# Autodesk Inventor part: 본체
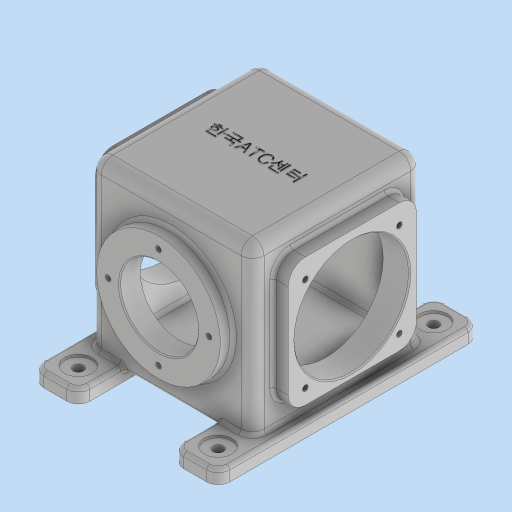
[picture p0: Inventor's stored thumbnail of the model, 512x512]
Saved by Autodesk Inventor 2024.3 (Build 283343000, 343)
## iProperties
Created: 2026-01
Part Number: 본체
Material: 일반
Document SubType Name: Modeling
Designer: PC2-02
Density: 1 g/cm^3
Appearance: 기본값
Author: PC2-02
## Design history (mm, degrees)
sketch "스케치1"
  geometry: L1 (-81, 114)-(81, 114); L2 (81, 114)-(81, -114); L3 (81, -114)-(-81, -114); L4 (-81, -114)-(-81, 114); 1 further point
  constraints: 8 end point, 2 parallel, 1 horizontal, 1 perpendicular
  dimensions: "d0" = 162 distance between parallel lines of L2 L4; "d1" = 81 distance from line of point (0, 0) L4; "d2" = 228 distance between parallel lines of L3 L1; "d3" = 114 distance from line of point (0, 0) L1
extrude "돌출1" new body sketch "스케치1" distance "d4" = 12; taper "d5" = 0 deg
sketch "스케치12"
  geometry: L1 (81, 114)-(-81, 114) reference; L2 (-81, -114)-(81, -114) reference; L3 (-41, 114)-(41, 114); L4 (41, 114)-(41, -114); L5 (41, -114)-(-41, -114); L6 (-41, -114)-(-41, 114); L7 (81, -114)-(81, 114) reference; L8 (-81, 114)-(-81, -114) reference; 3 further points
  constraints: 8 end point, 2 parallel, 2 point on line, 1 horizontal, 1 perpendicular
  dimensions: "d91" = 40 distance between parallel lines of L7 L4; "d92" = 40 distance between parallel lines of L8 L6
extrude "돌출7" cut sketch "스케치12" extent not by distance; stored distance "d93" = 0; taper "d94" = 0 deg
sketch "스케치2"
  geometry: L1 (71, 156)-(-71, 156); L2 (-71, 156)-(-71, 8); L3 (-71, 8)-(71, 8); L4 (71, 8)-(71, 156); L5 (81, 0)-(-81, 0) reference; 2 further points
  constraints: 8 end point, 2 parallel, 1 horizontal, 1 midpoint, 1 perpendicular
  dimensions: "d6" = 156 distance between parallel lines of L5 L1; "d7" = 142 distance between parallel lines of L2 L4; "d8" = 71 distance from line of point (0, 0) L4; "d90" = 8 distance between parallel lines of L5 L3
extrude "돌출2" join sketch "스케치2" stored distance "d9" = 148; taper "d10" = 0 deg
sketch "스케치3"
  geometry: L1 (-56, 140)-(56, 140); L2 (56, 140)-(56, 28); L3 (56, 28)-(-56, 28); L4 (-56, 28)-(-56, 140); L5 (-74, 156)-(-74, 12) reference; 2 further points
  constraints: 8 end point, 2 parallel, 1 horizontal, 1 midpoint, 1 perpendicular
  dimensions: "d11" = 112 distance between parallel lines of L2 L4; "d12" = 56 distance from line of point (0, 0) L4; "d13" = 112 distance between parallel lines of L3 L1; "d14" = 56 distance from line of point (-74, 84) L1
extrude "돌출3" join sketch "스케치3" stored distance "d15" = 168; taper "d16" = 0 deg
sketch "스케치4"
  geometry: L1 (-81, 0)-(81, 0) reference; C1 r 54 at (0, 82); 2 further points
  constraints: 1 centre point, 1 midpoint, 1 vertical alignment
  dimensions: "d17" = 108 diameter of C1; "d18" = 82 distance from line of L1 C1.centre
extrude "돌출4" join sketch "스케치4" distance "d19" = 11; taper "d20" = 0 deg
sketch "스케치6"
  geometry: L1 (-28, 56)-(-140, 56) reference; L2 (-140, 56)-(-140, -56) reference; L3 (0, -114)-(0, 114) reference; 2 further points
  dimensions: "d25" = 56 distance from line of L1 point (-82, 0); "d112" = 82 distance from line of L3 point (-82, 0)
hole "구멍1" sketch "스케치6" at (-82, 0) diameter "d27" = 100; stored, may be unused: countersink angle "d31" = 90 deg, drill point angle "d33" = 118 deg; dims "d28" = 6, "d29" = 4, "d30" = 2, "d32" = 8
sketch "스케치7"
  geometry: C1 r 54 at (0, 0) reference; 2 further points
  constraints: 1 coincident
hole "구멍2" sketch "스케치7" at (0, 0) diameter "d34" = 68; stored, may be unused: countersink angle "d38" = 90 deg, drill point angle "d40" = 118 deg; dims "d35" = 6, "d36" = 4, "d37" = 2, "d39" = 8
sketch "스케치8"
  geometry: L1 (-67, 149)-(67, 149); L2 (67, 149)-(67, 15); L3 (67, 15)-(-67, 15); L4 (-67, 15)-(-67, 149); L5 (74, 12)-(74, 156) reference; L6 (-74, 156)-(74, 156) reference; L7 (-74, 156)-(-74, 12) reference; L8 (74, 12)-(114, 12) reference; L9 (74, 8)-(-74, 8) reference; 1 further point
  constraints: 8 end point, 2 parallel, 1 horizontal, 1 perpendicular
  dimensions: "d41" = 7 distance between parallel lines of L5 L2; "d42" = 7 distance between parallel lines of L6 L1; "d44" = 7 distance between parallel lines of L4 L7; "d111" = 7 distance between parallel lines of L9 L3
extrude "돌출6" cut sketch "스케치8" stored distance "d45" = 122; taper "d46" = 0 deg
sketch "스케치9"
  geometry: 2 further points
  dimensions: "d47" = 61 horizontal distance of point (61, 94) point (0, 0); "d48" = 94 vertical distance of point (0, 0) point (61, 94)
hole "구멍3" sketch "스케치9" at (61, 94) diameter "d49" = 9; stored, may be unused: countersink angle "d53" = 90 deg, drill point angle "d55" = 118 deg; dims "d50" = 6, "d51" = 24, "d52" = 2, "d54" = 8
sketch "스케치10" dims "d62" = 88
  geometry: C1 r 54 at (0, 0) reference; 3 further points
  constraints: 2 vertical alignment, 3 other
hole "구멍4" sketch "스케치10" at (0, 44) diameter "d63" = 4.917; stored, may be unused: countersink angle "d67" = 90 deg, drill point angle "d69" = 118 deg; dims "d64" = 12, "d65" = 4, "d66" = 2, "d68" = 14
sketch "스케치11"
  geometry: C1 r 50 at (-82, 0) reference; 2 further points
  dimensions: "d73" = 41 vertical distance of point (-123, 41) point (0, 0); "d74" = 41 horizontal distance of C1.centre point (-123, 41)
hole "구멍5" sketch "스케치11" at (-123, 41) diameter "d75" = 4.917; stored, may be unused: countersink angle "d79" = 90 deg, drill point angle "d81" = 118 deg; dims "d76" = 12, "d77" = 4, "d78" = 2, "d80" = 14
fillet "모깎기1" dims "d88" = 10
fillet "모깎기2" dims "d89" = 10
fillet "모깎기9" dims "d109" = 3
fillet "모깎기10" dims "d110" = 3
fillet "모깎기3" dims "d96" = 3
fillet "모깎기5" dims "d98" = 15
fillet "모깎기6" dims "d99" = 3
fillet "모깎기7" dims "d100" = 3
fillet "모깎기8" dims "d101" = 3
chamfer "모따기1" distance "d102" = 1; stored, may be unused: second distance "d103" = 2, angle "d104" = 45 deg
sketch "스케치13"
  geometry: L1 (16, 70.5)-(106, 70.5); L2 (106, 70.5)-(106, 57.5); L3 (106, 57.5)-(16, 57.5); L4 (16, 57.5)-(16, 70.5); L5 (16, 64)-(106, 64); L6 (61, 70.5)-(61, 57.5); 2 further points
  constraints: 5 midpoint, 4 end point, 1 coincident, 1 vertical, 2 other
  dimensions: "d105" = 13 distance between parallel lines of L1 L3; "d106" = 90 distance between parallel lines of L4 L2
feature "엠보싱1" sketch "스케치13" dims "d0" = 162, "d1" = 81, "d2" = 228, "d3" = 114, "d107" = 0.5, "d108" = 0
feature "̻耀̽耀̿耀́耀̓耀ͅ耀͇耀͉耀" dims "d0" = 162, "d1" = 81, "d2" = 228, "d3" = 114, "d4" = 12, "d5" = 0, "d6" = 156, "d7" = 142, "d8" = 71, "d9" = 148, "d10" = 0, "d11" = 112, "d12" = 56, "d13" = 112, "d14" = 56, "d15" = 168, "d16" = 0, "d17" = 108, "d18" = 82, "d19" = 11, "d20" = 0, "d25" = 56, "d27" = 100, "d28" = 6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
node "솔리드1"
pattern_linear "직사각형 패턴1" dims "d58" = 188, "d61" = 122
pattern_circular "원형 패턴1" dims angle "d71" = 360 deg
pattern_linear "직사각형 패턴2" dims "d84" = 82, "d87" = 82
mirror "미러1"
feature "A9D066F2-1C7D-4E18-AEED-F7BC21143FA4" dims "d49" = 9, "d50" = 6, "d51" = 24, "d52" = 2, "d53" = 90 deg, "d54" = 8, "d55" = 118 deg
